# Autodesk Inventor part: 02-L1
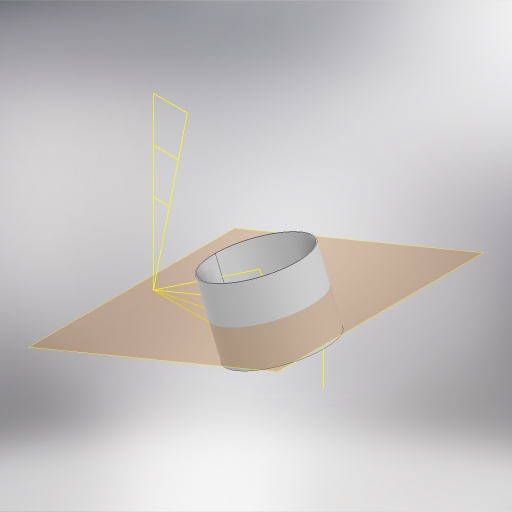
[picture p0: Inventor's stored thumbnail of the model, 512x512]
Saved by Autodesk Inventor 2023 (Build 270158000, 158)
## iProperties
Created: 2023-01
Part Number: 02-L1
Material: Generic
Document SubType Name: Sheet Metal
Designer: Nelson C Agudelo A
Density: 1 g/cm^3
Flat Pattern Width: 84.8759 cm
Flat Pattern Length: 10.2937 cm
Flat Pattern Area: 873.689 cm^2
Sheet Metal Rule: Default_mm
Sheet Metal Width: 848,759 mm
Sheet Metal Length: 102,937 mm
Sheet Metal Area: 87368,870 mm^2
Appearance: Default
Author: Nelson C Agudelo A
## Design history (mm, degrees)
derived "01-Esquema Codo Mitrado.ipt"
  sketch "Sketch1"
    geometry: L1 (0, 0)-(381, 0) reference; L2 (381, 0)-(381, 75.786) reference; L3 (244.5, 0)-(244.5, 48.634) reference; L4 (517.5, 0)-(517.5, 102.937) reference; L5 (0, 0)-(517.5, 102.937) reference; L6 (0, 0)-(0, 381) reference; L7 (0, 244.5)-(48.634, 244.5) reference; L8 (0, 517.5)-(102.937, 517.5) reference; L9 (0, 381)-(0, 517.5) reference; L10 (0, 0)-(102.937, 517.5) reference; L11 (0, 381)-(75.786, 381) reference; L12 (0, 0)-(322.996, 215.819) reference; L13 (381, 75.786)-(322.996, 215.819) reference; L14 (0, 0)-(351.998, 145.802) reference; 1 further point
workplane "Work Plane1"
node "Contour Flange2"
  sketch "Sketch4"
    geometry: L1 (0, 381)-(-0.05, 244.5); L2 (0, 381)-(0.05, 244.5); L3 (0.05, 244.5)-(-0.05, 244.5); A1 r 136.5 centre (0, 381) between (0.05, 244.5) and (-0.05, 244.5); 3 further points
    constraints: 6 end point, 2 point on circle, 1 centre point, 1 coincident, 1 midpoint, 1 vertical alignment
    dimensions: "d27" = 273 diameter of A1 (= ODtuberia); "d28" = 0.1 distance of L2.end L1.end
sketch "Sketch5"
  geometry: 1 further point
body "Solid2"
face "Plate2" dims "d29" = 2.5 (= Thickness), "d30" = 2.5 (= BendReliefWidth), "d31" = 1.25 (= BendReliefDepth), "d32" = 5 (= MinimumRemnant), "d33" = 2.5 (= TransitionRadius), "d34" = 205.8743 (= L1 + 2 x Recorte), "d35" = 2.5 (= BendRadius), "d36" = 2.5, "d37" = 10 (= CornerReliefSize), "d38" = 2.5 (= GapSize), "d39" = 2.5 (= JacobiRadiusSize), "SeamGap" = 0.01
bend "Bend2" dims "d29" = 2.5 (= Thickness), "d30" = 2.5 (= BendReliefWidth), "d31" = 1.25 (= BendReliefDepth), "d32" = 5 (= MinimumRemnant), "d33" = 2.5 (= TransitionRadius), "d35" = 2.5 (= BendRadius), "d36" = 2.5, "SeamGap" = 0.01
feature "Corner2" dims "d36" = 2.5, "d37" = 10 (= CornerReliefSize), "d38" = 2.5 (= GapSize), "d39" = 2.5 (= JacobiRadiusSize)
feature "Definition1"
other parameters: "Thickness" = 2.5 (derived), "BendRadius" = 2.5 (= Thickness), "BendReliefWidth" = 2.5 (= Thickness), "BendReliefDepth" = 1.25 (= 0.5 x Thickness), "MinimumRemnant" = 5 (= 2 x Thickness), "TransitionRadius" = 2.5 (= BendRadius), "JacobiRadiusSize" = 2.5 (= BendRadius), "GapSize" = 2.5 (= Thickness), "d1" = 381, "d2" = 75.78561, "d3" = 90 deg, "d4" = 273, "d5" = 136.5, "d6" = 273, "d8" = 273, "d9" = 136.5, "DL1" = 22.5 deg, "d13" = 151.57122, "L2" = 75.78561, "L1" = 151.57122, "Recorte" = 27.15154, "D" = 90 deg, "E1" = 381, "ODtuberia" = 273, "DL2" = 1.9635, "d14" = 27.15154, "d26" = 22.5 deg (= DL1), "BendRadius" = 2.5, "BendReliefDepth" = 1.25, "BendReliefWidth" = 2.5, "D" = 90 deg, "DL1" = 22.5 deg, "DL2" = 1.9635, "E1" = 381, "GapSize" = 2.5, "JacobiRadiusSize" = 2.5, "L1" = 151.57122, "L2" = 75.78561, "MinimumRemnant" = 5, "ODtuberia" = 273, "Recorte" = 27.15154, "Thickness" = 2.5, "TransitionRadius" = 2.5
